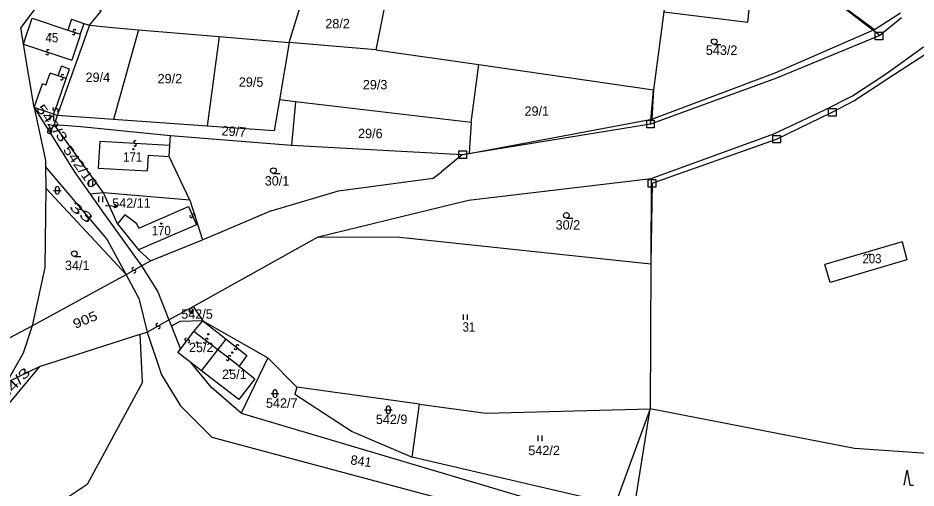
# Model space of a CAD drawing. Extents: x -680102 to -677253, y -1007548 to -1006096.
# Drawn here: x -679757 to -679518.8, y -1007322.1 to -1007197.5 of the extents above; entities that cross this region are included whole.
import ezdxf
from ezdxf.enums import TextEntityAlignment as Align

# ---------------------------------------------------------------- set-up
doc = ezdxf.new("R2010")
doc.units = 0
for name, color, linetype, lineweight in [('1', 7, 'Continuous', 25), ('11', 7, 'Continuous', 25), ('16', 7, 'Continuous', 25), ('24', 7, 'Continuous', 25), ('25', 7, 'Continuous', 25), ('35', 7, 'Continuous', 25), ('4', 7, 'Continuous', 25)]:
    doc.layers.add(name, color=color, linetype=linetype, lineweight=lineweight)
doc.layers.add('18', color=7, linetype='Continuous')
doc.layers.add('19', color=7, linetype='Continuous')

msp = doc.modelspace()

# ---------------------------------------------------------------- linework, layer by layer
at = {"layer": '1'}
for p, q in [((-679553.95, -1007182.63), (-679529.88, -1007200.6)), ((-679746.11, -1007186.68), (-679756.3, -1007200.04)), ((-679563.43, -1007198.62), (-679562.84, -1007192.91)), ((-679585.73, -1007195.92), (-679563.43, -1007198.62)), ((-679529.88, -1007200.6), (-679522.98, -1007196.16)), ((-679753.26, -1007197.57), (-679743.77, -1007200.72)), ((-679738.05, -1007199.47), (-679746.24, -1007222.44)), ((-679742.83, -1007197.88), (-679743.77, -1007200.72)), ((-679742.83, -1007197.88), (-679739.54, -1007198.97)), ((-679739.54, -1007198.97), (-679738.05, -1007199.47)), ((-679738.05, -1007199.47), (-679732.79, -1007200)), ((-679755.56, -1007204.45), (-679756.3, -1007200.04)), ((-679725.08, -1007200.66), (-679731.68, -1007224.45)), ((-679755.56, -1007204.45), (-679755.18, -1007203.32)), ((-679752.73, -1007221.24), (-679755.56, -1007204.45)), ((-679703.63, -1007202.48), (-679706.88, -1007226.2)), ((-679703.63, -1007202.48), (-679685.14, -1007204.06)), ((-679526.67, -1007212.28), (-679516.84, -1007205.14)), ((-679636.86, -1007225.28), (-679634.81, -1007209.9)), ((-679535.68, -1007218.13), (-679526.67, -1007212.28)), ((-679588.44, -1007216.55), (-679588.92, -1007224.31)), ((-679543.19, -1007221.98), (-679535.68, -1007218.13)), ((-679747.56, -1007223.06), (-679752.73, -1007221.24)), ((-679752.73, -1007221.24), (-679749.7, -1007235.34)), ((-679752.73, -1007221.24), (-679749.41, -1007226.5)), ((-679683.4, -1007219.72), (-679684.48, -1007231.21)), ((-679746.59, -1007223.4), (-679747.56, -1007223.06)), ((-679731.68, -1007224.45), (-679746.59, -1007223.4)), ((-679747.43, -1007225.75), (-679748.66, -1007227.71)), ((-679747.43, -1007225.75), (-679740.31, -1007226.31)), ((-679734.32, -1007243.87), (-679747.43, -1007225.75)), ((-679636.86, -1007225.28), (-679637.36, -1007233.42)), ((-679740.31, -1007226.31), (-679716.59, -1007228.7)), ((-679716.71, -1007231.31), (-679716.59, -1007228.7)), ((-679716.59, -1007228.7), (-679684.48, -1007231.21)), ((-679716.89, -1007234.24), (-679716.71, -1007231.31)), ((-679684.48, -1007231.21), (-679639.09, -1007233.74)), ((-679711.43, -1007245.82), (-679716.89, -1007234.24)), ((-679639.09, -1007233.74), (-679644.67, -1007238.28)), ((-679733.43, -1007256.06), (-679749.68, -1007236.92)), ((-679742.13, -1007238.27), (-679737.83, -1007244.27)), ((-679589.05, -1007240.05), (-679589.15, -1007262.7)), ((-679749.6, -1007242.65), (-679749.87, -1007263.68)), ((-679728.36, -1007265.52), (-679749.6, -1007242.65)), ((-679711.43, -1007245.82), (-679734.32, -1007243.87)), ((-679711.43, -1007245.82), (-679708.06, -1007256.34)), ((-679689.89, -1007248.62), (-679706.47, -1007255.7)), ((-679730.64, -1007252.08), (-679725.84, -1007258.02)), ((-679721.83, -1007261.94), (-679708.06, -1007256.34)), ((-679710.54, -1007274), (-679677.41, -1007255.58)), ((-679706.47, -1007255.7), (-679708.06, -1007256.34)), ((-679522.55, -1007256.89), (-679543.05, -1007262.88)), ((-679725.84, -1007258.02), (-679725.09, -1007258.98)), ((-679725.09, -1007258.98), (-679721.83, -1007261.94)), ((-679749.87, -1007263.68), (-679753.24, -1007279.15)), ((-679724.22, -1007263.25), (-679721.83, -1007261.94)), ((-679724.22, -1007263.25), (-679719.95, -1007270.12)), ((-679589.15, -1007262.7), (-679589.32, -1007301.17)), ((-679541.66, -1007267.65), (-679543.05, -1007262.88)), ((-679753.24, -1007279.15), (-679728.36, -1007265.52)), ((-679719.95, -1007270.12), (-679716.99, -1007277.59)), ((-679725, -1007271.78), (-679722.75, -1007280.79)), ((-679716.99, -1007277.59), (-679710.54, -1007274)), ((-679710.54, -1007274), (-679708, -1007277.84)), ((-679716.99, -1007277.59), (-679716.34, -1007279.21)), ((-679714.06, -1007278), (-679716.34, -1007279.21)), ((-679708, -1007277.84), (-679714.06, -1007278)), ((-679708, -1007277.84), (-679701.81, -1007282.65)), ((-679753.24, -1007279.15), (-679755.61, -1007286.35)), ((-679716.34, -1007279.21), (-679713.93, -1007285.32)), ((-679724.02, -1007294.07), (-679724.57, -1007281.37)), ((-679714.62, -1007286.21), (-679713.93, -1007285.32)), ((-679755.61, -1007286.35), (-679760.1, -1007294.19)), ((-679751.31, -1007289.93), (-679772.5, -1007315.36)), ((-679760.1, -1007294.19), (-679751.31, -1007289.93)), ((-679705.69, -1007295.52), (-679711.1, -1007288.93)), ((-679697.83, -1007302.32), (-679705.69, -1007295.52)), ((-679650.55, -1007299.91), (-679632.95, -1007302.33)), ((-679632.95, -1007302.33), (-679589.32, -1007301.17)), ((-679535.21, -1007311.65), (-679589.32, -1007301.17)), ((-679456.86, -1007317.08), (-679535.21, -1007311.65))]:
    msp.add_line(p, q, dxfattribs=at)
for points in [[(-679658.42, -1007187.35), (-679662.15, -1007205.98), (-679685.14, -1007204.06), (-679677.38, -1007178.96)], [(-679738.05, -1007199.47), (-679734.98, -1007195.76), (-679746.11, -1007186.68)], [(-679584.41, -1007185.88), (-679585.73, -1007195.92), (-679588.44, -1007216.55)], [(-679755.18, -1007203.32), (-679753.43, -1007198.07), (-679753.26, -1007197.57)], [(-679732.79, -1007200), (-679725.08, -1007200.66), (-679703.63, -1007202.48)], [(-679588.92, -1007224.31), (-679556.2, -1007212.07), (-679529.88, -1007200.6)], [(-679685.14, -1007204.06), (-679687.68, -1007219.27), (-679689.05, -1007227.45)], [(-679662.15, -1007205.98), (-679634.81, -1007209.9), (-679588.44, -1007216.55)], [(-679636.86, -1007225.28), (-679683.4, -1007219.72), (-679687.68, -1007219.27)], [(-679746.24, -1007222.44), (-679746.59, -1007223.4), (-679747.43, -1007225.75)], [(-679589.05, -1007240.05), (-679556.52, -1007228.21), (-679543.19, -1007221.98)], [(-679689.05, -1007227.45), (-679706.88, -1007226.2), (-679731.68, -1007224.45)], [(-679639.09, -1007233.74), (-679637.36, -1007233.42), (-679588.92, -1007224.31)], [(-679749.41, -1007226.5), (-679748.66, -1007227.71), (-679742.13, -1007238.27)], [(-679749.7, -1007235.34), (-679749.68, -1007236.92), (-679749.6, -1007242.65)], [(-679689.89, -1007248.62), (-679671.98, -1007243.39), (-679646.95, -1007240.02), (-679644.67, -1007238.28)], [(-679677.41, -1007255.58), (-679637.58, -1007245.83), (-679589.05, -1007240.05)], [(-679730.64, -1007252.08), (-679734.32, -1007243.87), (-679737.83, -1007244.27)], [(-679737.83, -1007244.27), (-679734.21, -1007249.32), (-679724.22, -1007263.25)], [(-679725, -1007271.78), (-679728.36, -1007265.52), (-679733.43, -1007256.06)], [(-679677.41, -1007255.58), (-679655.71, -1007255.62), (-679589.15, -1007262.7)], [(-679522.55, -1007256.89), (-679521.28, -1007261.64), (-679541.66, -1007267.65)], [(-679708, -1007277.84), (-679690.78, -1007287.62), (-679683.07, -1007295.43)], [(-679751.31, -1007289.93), (-679724.57, -1007281.37), (-679722.75, -1007280.79)], [(-679722.75, -1007280.79), (-679718.93, -1007292.15), (-679713.9, -1007300.35), (-679705.61, -1007308.64), (-679612.54, -1007333.58)], [(-679708.32, -1007291.08), (-679704.02, -1007285.52), (-679701.81, -1007282.65)], [(-679708.32, -1007291.08), (-679711.1, -1007288.93), (-679714.62, -1007286.21)], [(-679690.78, -1007287.62), (-679697.83, -1007302.32), (-679610.92, -1007328.07), (-679593.69, -1007328.25), (-679589.32, -1007301.17), (-679598.63, -1007326.55), (-679652.45, -1007313.98)], [(-679724.02, -1007294.07), (-679738.68, -1007321.18), (-679759.61, -1007335.18), (-679777.7, -1007359.21)]]:
    msp.add_lwpolyline(points, dxfattribs=at)
msp.add_lwpolyline([(-679652.45, -1007313.98), (-679650.55, -1007299.91), (-679683.07, -1007295.43), (-679683.57, -1007297.29), (-679668.41, -1007307.17)], close=True, dxfattribs=at)
at = {"layer": '11'}
for p, q in [((-679589.27, -1007225.64), (-679639.22, -1007233.8)), ((-679588.85, -1007241.34), (-679589.15, -1007262.7))]:
    msp.add_line(p, q, dxfattribs=at)
for points in [[(-679522.66, -1007197.48), (-679528.41, -1007202.14), (-679553.95, -1007182.63)], [(-679528.41, -1007202.14), (-679555.85, -1007213.46), (-679589.27, -1007225.64), (-679588.44, -1007216.55)], [(-679588.85, -1007241.34), (-679555.81, -1007229.66), (-679541.1, -1007222.54), (-679535.31, -1007219.48), (-679526.32, -1007213.61), (-679514.72, -1007206.1), (-679487.44, -1007211.36)]]:
    msp.add_lwpolyline(points, dxfattribs=at)
at = {"layer": '16'}
for p, q in [((-679733.83, -1007247.21), (-679733.58, -1007247.23)), ((-679733.58, -1007247.23), (-679730.584, -1007247.381))]:
    msp.add_line(p, q, dxfattribs=at)
msp.add_lwpolyline([(-679731.558, -1007246.832), (-679730.584, -1007247.381), (-679731.608, -1007247.83)], dxfattribs=at)
at = {"layer": '24'}
for radius in [0.5, 0.022]:
    msp.add_circle((-679748.66, -1007227.71), radius, dxfattribs=at)
msp.add_arc((-679748.661, -1007227.147), 0.437, 328.35109, 209.97456, dxfattribs=at)
at = {"layer": '25'}
for p, q in [((-679572.37, -1007204.55), (-679570.62, -1007204.55)), ((-679748.507, -1007224.605), (-679748.507, -1007223.105)), ((-679747.473, -1007224.605), (-679747.473, -1007223.105)), ((-679689.26, -1007238.75), (-679687.51, -1007238.75)), ((-679738.237, -1007242.145), (-679738.237, -1007240.645)), ((-679737.203, -1007242.145), (-679737.203, -1007240.645)), ((-679747.58, -1007243.23), (-679745.58, -1007243.23)), ((-679747.08, -1007243.73), (-679747.08, -1007242.73)), ((-679746.08, -1007242.73), (-679746.08, -1007243.73)), ((-679735.537, -1007246.335), (-679735.537, -1007244.835)), ((-679734.503, -1007246.335), (-679734.503, -1007244.835)), ((-679611.58, -1007250.6), (-679609.83, -1007250.6)), ((-679742.06, -1007260.75), (-679740.31, -1007260.75)), ((-679711.799, -1007275.15), (-679710.4, -1007275.15)), ((-679711.449, -1007275.5), (-679711.449, -1007274.8)), ((-679710.75, -1007274.8), (-679710.75, -1007275.5)), ((-679638.837, -1007277.595), (-679638.837, -1007276.095)), ((-679637.803, -1007277.595), (-679637.803, -1007276.095)), ((-679689.85, -1007297.11), (-679687.85, -1007297.11)), ((-679689.35, -1007297.61), (-679689.35, -1007296.61)), ((-679688.35, -1007296.61), (-679688.35, -1007297.61)), ((-679659.81, -1007301.41), (-679657.81, -1007301.41)), ((-679659.31, -1007301.91), (-679659.31, -1007300.91)), ((-679658.31, -1007300.91), (-679658.31, -1007301.91)), ((-679619.047, -1007309.745), (-679619.047, -1007308.245)), ((-679618.013, -1007309.745), (-679618.013, -1007308.245))]:
    msp.add_line(p, q, dxfattribs=at)
msp.add_lwpolyline([(-679640.09, -1007232.74), (-679638.09, -1007232.74), (-679638.09, -1007234.74), (-679640.09, -1007234.74)], close=True, dxfattribs=at)
msp.add_lwpolyline([(-679521.99, -1007321.39), (-679521.24, -1007317.39), (-679520.49, -1007321.39), (-679519.49, -1007321.39)], dxfattribs=at)
for centre, radius in [((-679748.51, -1007201.78), 0.175), ((-679572.37, -1007203.8), 0.75), ((-679726.4, -1007232.31), 0.175), ((-679689.26, -1007238), 0.75), ((-679611.58, -1007249.85), 0.75), ((-679719.02, -1007252.03), 0.175), ((-679742.06, -1007260), 0.75), ((-679531.18, -1007260.26), 0.175), ((-679706.5, -1007281.39), 0.175), ((-679709.57, -1007283.59), 0.175), ((-679700.17, -1007286.23), 0.175), ((-679700.79, -1007290.89), 0.175)]:
    msp.add_circle(centre, radius, dxfattribs=at)
for centre, radius, start, end in [((-679742.251, -1007201.618), 0.368, 198.82963, 70.83079), ((-679742.01, -1007200.922), 0.368, 18.82645, 250.97639), ((-679749.292, -1007206.938), 0.368, 198.68243, 70.68242), ((-679749.05, -1007206.243), 0.367, 18.55929, 250.92552), ((-679745.42, -1007213.598), 0.368, 198.8245, 70.97496), ((-679745.179, -1007212.902), 0.368, 18.8282, 250.83114), ((-679747.432, -1007221.697), 0.367, 106.50274, 338.75219), ((-679746.747, -1007221.965), 0.369, 286.52317, 158.72588), ((-679725.974, -1007230.422), 0.368, 34.03575, 265.96077), ((-679726.024, -1007231.157), 0.367, 214.07842, 86.25915), ((-679746.58, -1007242.73), 0.5, 0.101, 180.00143), ((-679746.58, -1007243.73), 0.5, 180.10243, 0.00286), ((-679710.391, -1007249.807), 0.368, 330.48042, 202.87304), ((-679711.071, -1007250.092), 0.369, 150.58416, 22.31552), ((-679726.464, -1007264.066), 0.368, 65.99873, 298.23982), ((-679726.116, -1007264.715), 0.369, 246.00793, 118.16771), ((-679711.1, -1007274.799), 0.349, 359.86439, 180.16514), ((-679711.1, -1007275.5), 0.349, 180.10243, 0.00286), ((-679720.046, -1007278.867), 0.368, 66.41544, 298.58797), ((-679719.695, -1007279.515), 0.369, 246.14999, 118.31559), ((-679712.429, -1007282.773), 0.368, 89.65803, 321.85409), ((-679711.851, -1007283.229), 0.369, 269.53633, 141.61112), ((-679707.416, -1007283.39), 0.368, 179.69486, 52.07076), ((-679706.962, -1007282.811), 0.369, 359.84759, 231.86424), ((-679699.281, -1007285.097), 0.369, 179.22511, 51.17346), ((-679698.821, -1007284.522), 0.368, 359.08004, 231.51227), ((-679701.416, -1007287.97), 0.368, 179.69486, 52.07076), ((-679700.962, -1007287.391), 0.369, 359.84759, 231.86424), ((-679688.85, -1007296.61), 0.5, 0.101, 180.00143), ((-679688.85, -1007297.61), 0.5, 180.10243, 0.00286), ((-679658.81, -1007300.91), 0.5, 0.101, 180.00143), ((-679658.81, -1007301.91), 0.5, 180.10243, 0.00286)]:
    msp.add_arc(centre, radius, start, end, dxfattribs=at)
at = {"layer": '35'}
for points in [[(-679529.65, -1007201.31), (-679527.65, -1007201.31), (-679527.65, -1007203.31), (-679529.65, -1007203.31)], [(-679542.06, -1007221.52), (-679540.06, -1007221.52), (-679540.06, -1007223.52), (-679542.06, -1007223.52)], [(-679590.27, -1007224.64), (-679588.27, -1007224.64), (-679588.27, -1007226.64), (-679590.27, -1007226.64)], [(-679556.81, -1007228.66), (-679554.81, -1007228.66), (-679554.81, -1007230.66), (-679556.81, -1007230.66)], [(-679589.85, -1007240.34), (-679587.85, -1007240.34), (-679587.85, -1007242.34), (-679589.85, -1007242.34)]]:
    msp.add_lwpolyline(points, close=True, dxfattribs=at)
at = {"layer": '4'}
for p, q in [((-679739.54, -1007198.97), (-679740.48, -1007201.82)), ((-679743.77, -1007200.72), (-679740.48, -1007201.82)), ((-679740.48, -1007201.82), (-679740.65, -1007202.32)), ((-679755.56, -1007204.45), (-679742.77, -1007208.73)), ((-679740.65, -1007202.32), (-679742.77, -1007208.73)), ((-679746.38, -1007212.89), (-679745.5, -1007210.33)), ((-679743.34, -1007211.06), (-679745.5, -1007210.33)), ((-679749.59, -1007215.31), (-679748.51, -1007212.18)), ((-679746.38, -1007212.89), (-679748.51, -1007212.18)), ((-679744.22, -1007213.61), (-679746.38, -1007212.89)), ((-679752.73, -1007221.24), (-679750.53, -1007214.99)), ((-679749.59, -1007215.31), (-679750.53, -1007214.99)), ((-679747.56, -1007223.06), (-679746.62, -1007220.59)), ((-679728.71, -1007249.74), (-679730.64, -1007252.08)), ((-679724.99, -1007253.24), (-679711.77, -1007247.54)), ((-679728.36, -1007265.52), (-679724.22, -1007263.25)), ((-679722.75, -1007280.79), (-679716.99, -1007277.59)), ((-679710.35, -1007280.68), (-679708, -1007277.84)), ((-679764.86, -1007285.28), (-679753.24, -1007279.15)), ((-679713.93, -1007285.32), (-679710.35, -1007280.68))]:
    msp.add_line(p, q, dxfattribs=at)
for points in [[(-679746.62, -1007220.59), (-679744.22, -1007213.61), (-679743.34, -1007211.06)], [(-679716.71, -1007231.31), (-679735.28, -1007230.26), (-679735.74, -1007237.31), (-679722.64, -1007238.08), (-679722.4, -1007233.91), (-679716.89, -1007234.24)], [(-679724.99, -1007253.24), (-679725.47, -1007252.14), (-679728.71, -1007249.74)], [(-679711.77, -1007247.54), (-679709.7, -1007252.36), (-679725.09, -1007258.98)], [(-679698.37, -1007289.84), (-679704.02, -1007285.52), (-679710.35, -1007280.68)], [(-679701.81, -1007282.65), (-679696.29, -1007286.98), (-679698.37, -1007289.84), (-679694.18, -1007293.2), (-679698.44, -1007298.71), (-679708.32, -1007291.08)]]:
    msp.add_lwpolyline(points, dxfattribs=at)

# ---------------------------------------------------------------- texts
at = {"layer": '16'}
msp.add_text('542/11', height=2.5, dxfattribs=at).set_placement((-679726.929, -1007247.85), align=Align.CENTER)
at = {"layer": '18'}
for s, p in [('28/2', (-679675.51, -1007200.28)), ('543/2', (-679574.59, -1007207.31)), ('29/4', (-679739.09, -1007214.5)), ('29/2', (-679719.98, -1007214.86)), ('29/5', (-679698.45, -1007215.76)), ('29/3', (-679665.56, -1007216.46)), ('29/1', (-679622.68, -1007223.47)), ('29/6', (-679666.82, -1007229.39)), ('30/1', (-679691.57, -1007241.96)), ('30/2', (-679614.43, -1007253.63)), ('34/1', (-679744.54, -1007264.36)), ('542/5', (-679713.72, -1007277.26)), ('542/7', (-679691.25, -1007300.87)), ('542/9', (-679662.11, -1007305.17)), ('542/2', (-679621.67, -1007313.43))]:
    msp.add_text(s, height=2.5, dxfattribs=at).set_placement(p)
for s, rotation, width, p in [('542/3', 306.202, 1.35, (-679748.999, -1007226.114)), ('542/10', 305.602, 1.25, (-679741.481, -1007237.689))]:
    msp.add_text(s, height=2.5, rotation=rotation, dxfattribs=dict(at, width=width)).set_placement(p, align=Align.CENTER)
for s, rotation, p in [('29/7', 356.503, (-679699.83, -1007228.841)), ('841', 351.903, (-679666.198, -1007316.243))]:
    msp.add_text(s, height=2.5, rotation=rotation, dxfattribs=at).set_placement(p, align=Align.CENTER)
for s, rotation, width, p in [('33', 321.003, 1.8, (-679743.619, -1007247.911)), ('905', 22.3, 1.2, (-679741.841, -1007279.96)), ('34/3', 47, 1.55, (-679760.399, -1007298.998))]:
    msp.add_text(s, height=2.5, rotation=rotation, dxfattribs=dict(at, width=width)).set_placement(p)
msp.add_text('542/11', height=0.1, dxfattribs=at).set_placement((-679733.63, -1007247.01), align=Align.CENTER)
at = {"layer": '18', "width": 0.9}
msp.add_text('31', height=2.5, dxfattribs=at).set_placement((-679639.1, -1007280.69))
at = {"layer": '19', "width": 0.9}
for s, p in [('45', (-679749.71, -1007204)), ('203', (-679533.04, -1007262.57))]:
    msp.add_text(s, height=2.5, dxfattribs=at).set_placement(p)
for s, p in [('171', (-679726.6, -1007235.62)), ('170', (-679719.02, -1007255.15))]:
    msp.add_text(s, height=2.5, dxfattribs=at).set_placement(p, align=Align.CENTER)
at = {"layer": '19'}
for s, p in [('25/2', (-679711.66, -1007286.11)), ('25/1', (-679702.87, -1007293.24))]:
    msp.add_text(s, height=2.5, dxfattribs=at).set_placement(p)

doc.saveas('drawing.dxf')
